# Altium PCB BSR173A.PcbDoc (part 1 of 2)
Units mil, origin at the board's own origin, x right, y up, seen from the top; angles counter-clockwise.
Board outline 3000 x 1500 mil, 4 copper layers (Top Layer, Signal Layer 1, Signal Layer 2, Bottom Layer), stack 61.2 mil thick; 64 components, 17 nets, 119 pads, 82 vias.
Unrouted connection lines stored in the file: 2.
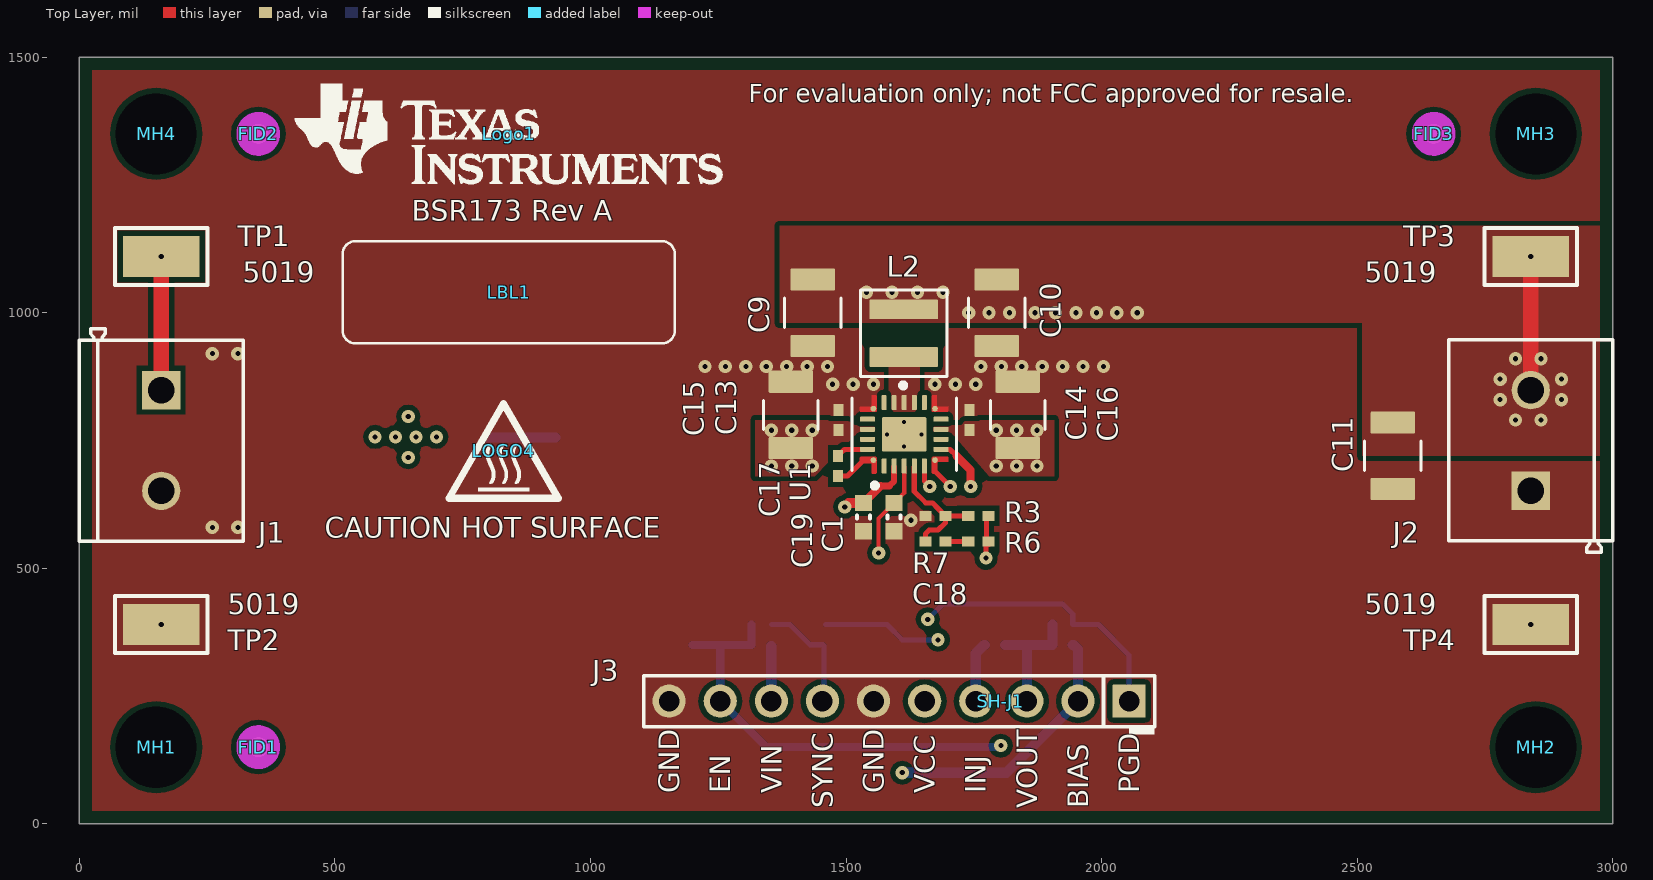
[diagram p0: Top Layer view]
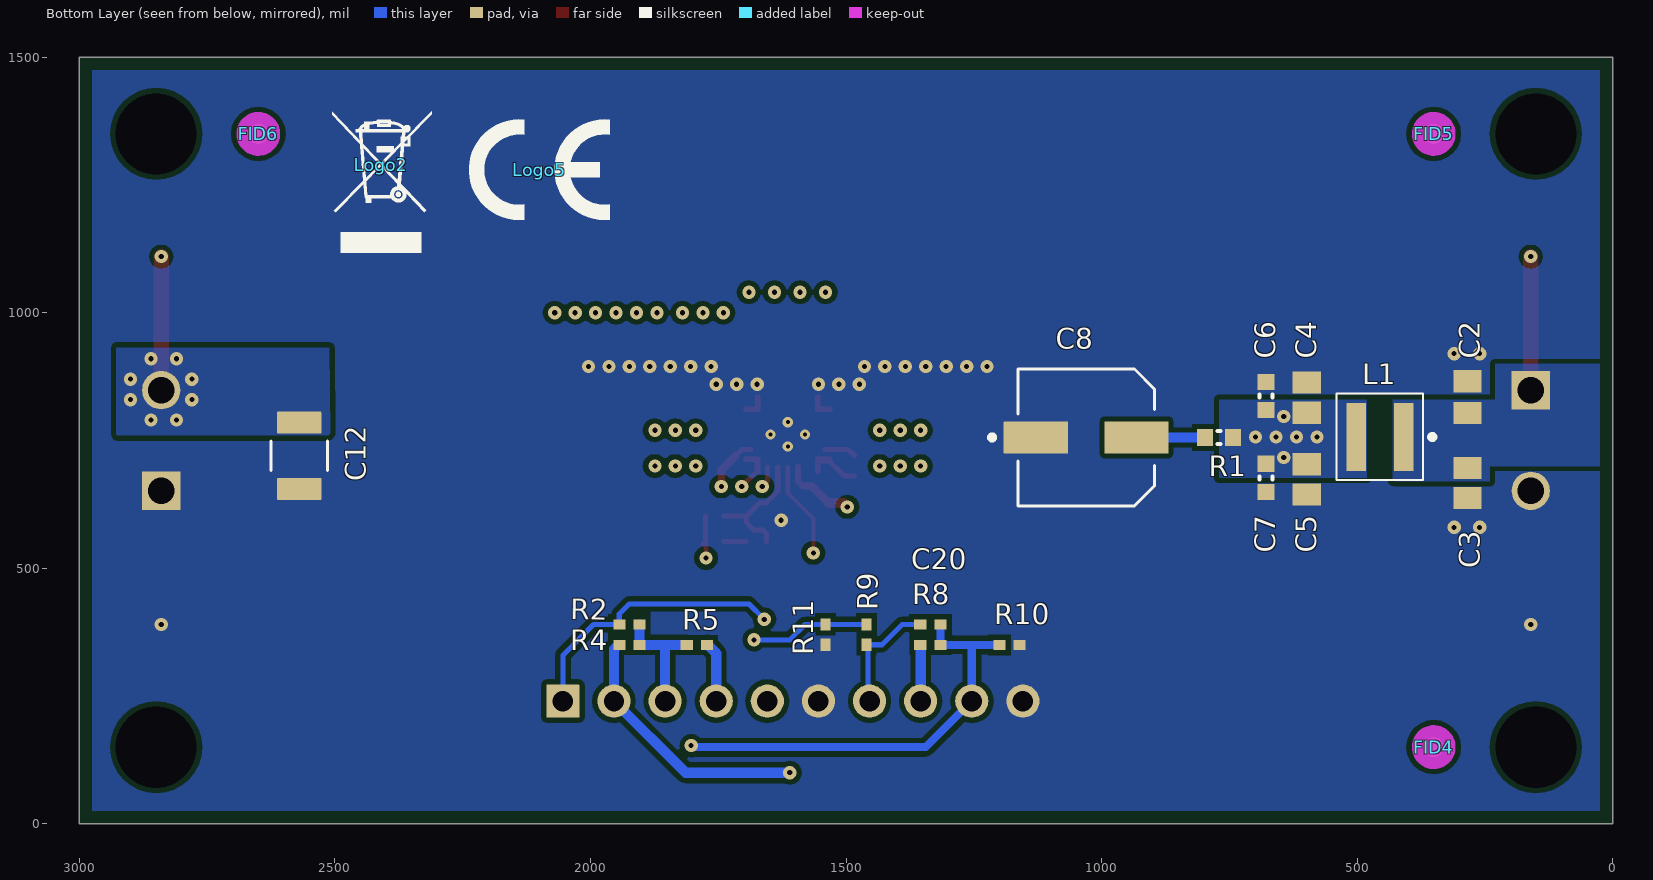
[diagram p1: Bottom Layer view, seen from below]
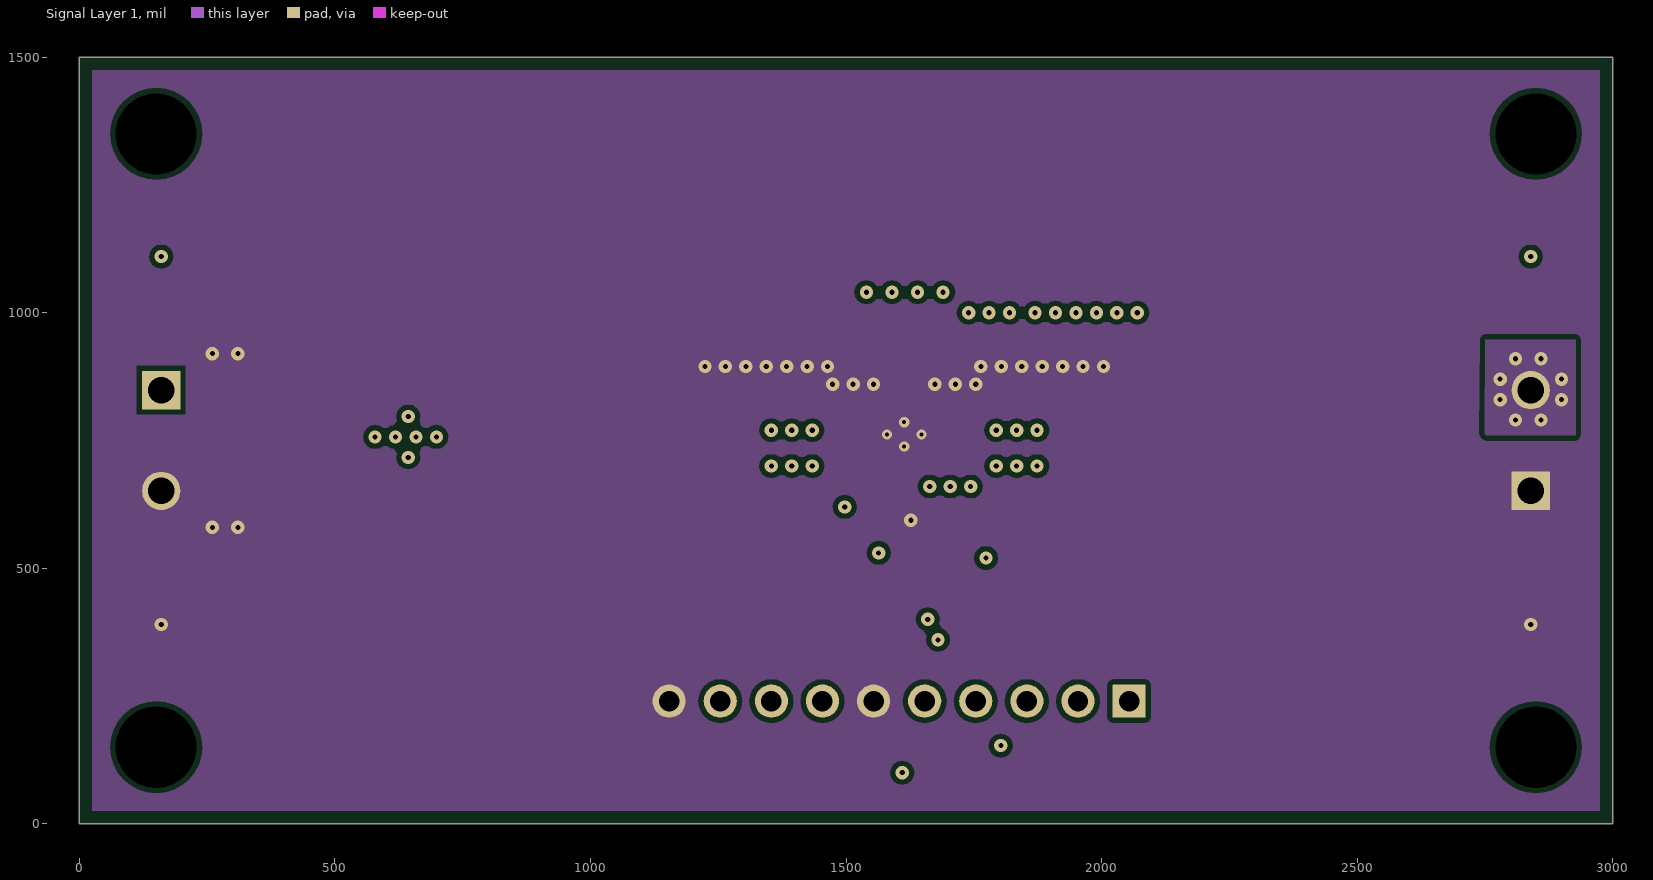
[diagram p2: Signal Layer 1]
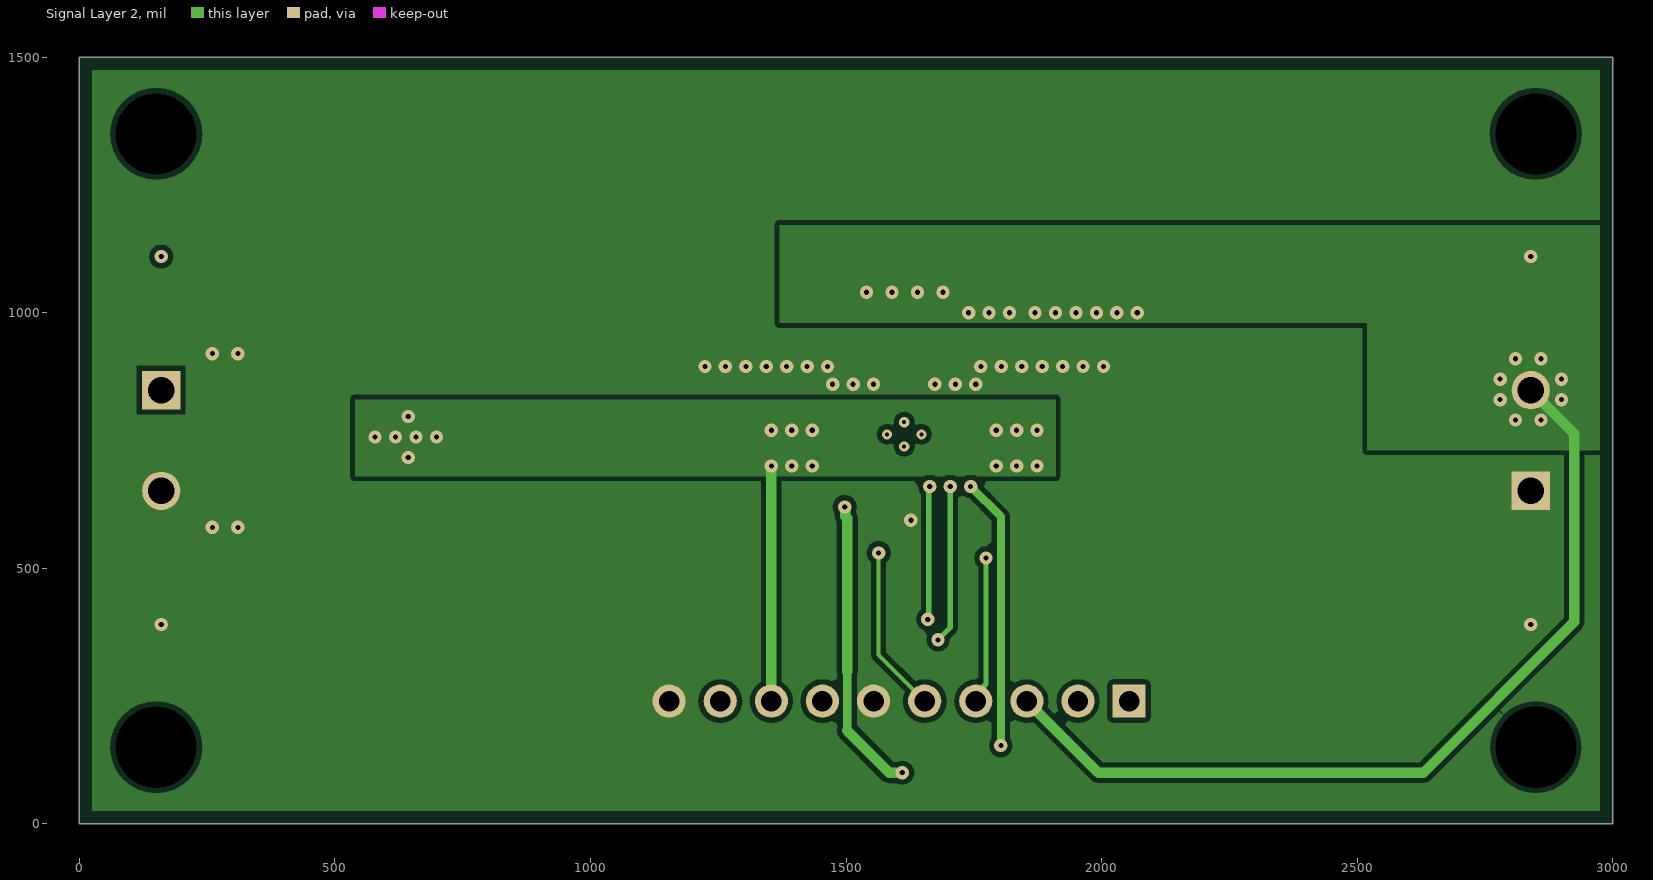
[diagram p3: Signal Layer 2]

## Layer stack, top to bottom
Top Solder: solder mask 0.4, Solder Resist, Dk 3.5
Top Layer: signal copper 2.8
Dielectric 1: prepreg 5, FR-4 High Tg, Dk 4.2
Signal Layer 1: signal copper 2.8
Dielectric 2: core 40, FR-4 High Tg, Dk 4.2
Signal Layer 2: signal copper 2.8
Dielectric 3: prepreg 5, FR-4 High Tg, Dk 4.2
Bottom Layer: signal copper 2.8
Bottom Solder: solder mask 0.4, Solder Resist, Dk 3.5

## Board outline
0,0 0,1500 3000,1500 3000,0

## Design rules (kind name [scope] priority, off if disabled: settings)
AcuteAngle [All] p1: minimum=4.50000000000000E+0001 checktracksonly=FALSE
AssemblyTestPointUsage [All] p1: valid=2
BoardOutlineClearance BoardOutlineClearance_1 [HasFootprint('Edge_Connector_EDAC_12x2')] p1: gap=0 ignorepadtopadclearanceinfootprint=FALSE
BoardOutlineClearance BoardOutlineClearance_MountingHoles [OnCopper and InComponentClass('Mounting Holes')] p2: gap=40 ignorepadtopadclearanceinfootprint=FALSE
BoardOutlineClearance BoardOutlineClearance_Poly [OnCopper and IsPoly] p3: gap=25 ignorepadtopadclearanceinfootprint=FALSE
BoardOutlineClearance [OnCopper and Not InComponentClass('Logo') and not InComponentClass('FiducialMark') and not InRegion(1000,500,4000,800) and not InPoly] p4: gap=65 ignorepadtopadclearanceinfootprint=FALSE
Clearance "Stitching VIN_PIN" [IsStitchingVia and InNet('VIN_PIN') vs (IsVia and (Not IsStitchingVia)) Or IsPad] p1: gap=9 ignorepadtopadclearanceinfootprint=FALSE
Clearance Clearance_Keepouts [((IsTrack Or IsArc) And Not InPoly) And IsFree and IsKeepOut vs ((IsTrack Or IsArc) And Not InPoly) And IsFree and IsKeepOut] p2: gap=0 ignorepadtopadclearanceinfootprint=FALSE
Clearance Clearance_Poly [InPolygon] p3: gap=10 ignorepadtopadclearanceinfootprint=FALSE
Clearance Clearance_FiducialMark [IsKeepOut and InComponentClass('FiducialMark') vs IsPad and InComponentClass('FiducialMark')] p4: gap=0 ignorepadtopadclearanceinfootprint=FALSE
Clearance [All] p5: gap=7.87 ignorepadtopadclearanceinfootprint=FALSE except(0: Arc-Hole Track-Hole SMDPad-Hole THPad-Hole Via-Hole Fill-Hole Poly-Hole Region-Hole Text-Hole)
ComponentClearance ComponentClearance_MountingHoles_FiducialMarks [InComponentClass('Mounting Holes') vs InComponentClass('FiducialMark')] p1: gap=50 collisioncheckmode=3 verticalgap=10 showdistances=FALSE
ComponentClearance ComponentClearance_Shunt [InComponentClass('Header') vs InComponentClass('Shunt')] p2: gap=0 collisioncheckmode=3 verticalgap=0 showdistances=FALSE
ComponentClearance ComponentClearance_Logo [InComponentClass('Logo')] p3: gap=50 collisioncheckmode=3 verticalgap=10 showdistances=FALSE
ComponentClearance ComponentClearance_ScrewToNut [(HasFootprint('NY PMS 440 0025 PH')) vs (HasFootprint('Keystone_1902C'))] p4: gap=5 collisioncheckmode=3 verticalgap=10 showdistances=FALSE
ComponentClearance ComponentClearance_MountingHoles [InComponentClass('Mounting Holes')] p5: gap=0 collisioncheckmode=3 verticalgap=100000 showdistances=FALSE
ComponentClearance ComponentClearance_SmallPassives [HasFootprint('0201*') or HasFootprint('0402*') or HasFootprint('0508') or HasFootprint('0603*') or HasFootprint('0612') or HasFootprint('0805*') or HasFootprint('0815*') or HasFootprint('0830*') or HasFootprint('1206*') or HasFootprint('1210*') or HasFootprint('1808*') or HasFootprint('1812*') or HasFootprint('1825*') or HasFootprint('2010*') or HasFootprint('2220*') or HasFootprint('2225*') or HasFootprint('2512*') or HasFootprint('2728*') or HasFootprint('3518*') vs HasFootprint('0201*') or HasFootprint('0402*') or HasFootprint('0508') or HasFootprint('0603*') or HasFootprint('0612') or HasFootprint('0805*') or HasFootprint('0815*') or HasFootprint('0830*') or HasFootprint('1206*') or HasFootprint('1210*') or HasFootprint('1808*') or HasFootprint('1812*') or HasFootprint('1825*') or HasFootprint('2010*') or HasFootprint('2220*') or HasFootprint('2225*') or HasFootprint('2512*') or HasFootprint('2728*') or HasFootprint('3518*')] p6: gap=14.96 collisioncheckmode=3 verticalgap=10 showdistances=FALSE
ComponentClearance ComponentClearance_THtoSMT [IsThruComponent vs IsSMTComponent] p7: gap=40 collisioncheckmode=3 verticalgap=30 showdistances=FALSE
ComponentClearance ComponentClearance_THtoTH [IsThruComponent vs IsThruComponent] p8: gap=30 collisioncheckmode=3 verticalgap=30 showdistances=FALSE
ComponentClearance [All] p9: gap=30 collisioncheckmode=3 verticalgap=10 showdistances=FALSE
DiffPairsRouting [All] p1: maxlimit=100 minlimit=10 mostfreqgap=10 toplayer_minwidth=15 toplayer_maxwidth=15 toplayer_prefwidth=15 midlayer1_minwidth=15 midlayer1_maxwidth=15 midlayer1_prefwidth=15 midlayer2_minwidth=15 midlayer2_maxwidth=15 midlayer2_prefwidth=15 bottomlayer_minwidth=15 bottomlayer_maxwidth=15 bottomlayer_prefwidth=15 maxuncoupledlength=1000
FabricationTestPointUsage TestPointUsage [All] p1: valid=2 allowmultiple=FALSE
FabricationTestpoint Testpoint [All] p1: side=3 testpointundercomponent=TRUE minsize=40 maxsize=100 preferedsize=60 minholesize=0 maxholesize=40 preferedholesize=32 testpointgrid=1 allowsidetop=TRUE allowsidebottom=TRUE usegrid=TRUE gridtolerance=0.01
FanoutControl Fanout_LCC [IsLCC] p1: bgadir=Out bgaviamode=Centered fanoutstyle=Auto fanoutdirection=Alternating viagrid=1 // Fanout_LCC (Default Rule)
FanoutControl Fanout_BGA [IsBGA] p2: bgadir=Out bgaviamode=Centered fanoutstyle=Auto fanoutdirection=Alternating viagrid=1 // Fanout_BGA (Default Rule)
FanoutControl Fanout_Default [All] p4: bgadir=Out bgaviamode=Centered fanoutstyle=Auto fanoutdirection=Alternating viagrid=1 // Fanout_Default (Default Rule)
FanoutControl Fanout_Small [(CompPinCount < 5)] p5: bgadir=Out bgaviamode=Centered fanoutstyle=Auto fanoutdirection=OutThenIn viagrid=1 // Fanout_Small (Default Rule)
HoleSize [All] p1: absolutevalues=TRUE maxlimit=251 minlimit=7.87 maxpercent=80.000 minpercent=20.000
MinimumAnnularRing MinimumAnnularRing_ThermalPadVias [IsVia and InAnyComponent] p1: minimumring=5.91
MinimumAnnularRing [All] p2: minimumring=7
MinimumSolderMaskSliver MinimumSolderMaskSliver_Logo [InComponentClass('Logo') vs InComponentClass('Logo')] p1: minsoldermaskwidth=0.7
MinimumSolderMaskSliver [All] p2: minsoldermaskwidth=3.94
PlaneConnect [All] p1: planeconnectstyle=Direct reliefexpansion=10 reliefentries=4 reliefconductorwidth=10 reliefairgap=10
PolygonConnect [All] p1: connectstyle=Direct reliefconductorwidth=10 reliefentries=4 polygonreliefangle="90 Angle" airgapwidth=10
RoutingVias ThermalPadVias [IsVia and InAnyComponent] p1: holewidth=7.87 width=19.68 viastyle="Through Hole" minholewidth=7.87 minwidth=19.68 maxholewidth=12.99 maxwidth=23.62
RoutingVias [All] p2: holewidth=16 width=34 viastyle="Through Hole" minholewidth=7.87 minwidth=20 maxholewidth=40 maxwidth=65
SilkToBoardRegionClearance [Not ((IsComment or IsDesignator) And (Hide <> 'False')) and not InRegion(1000,500,4000,800)] p1:
SilkToSilkClearance SilkToSilkClearance_Pb-FreeLogo [(HasFootprint('Pb-Free_Overlay_Medium') OR HasFootprint('Pb-Free_Overlay_Small')) vs (HasFootprint('Pb-Free_Overlay_Medium') OR HasFootprint('Pb-Free_Overlay_Small'))] p1: silktosilkclearance=0
SilkToSilkClearance [All] p2: silktosilkclearance=4
SilkToSolderMaskClearance SilkToComponentPadClearance [(IsPad or IsFill or IsRegion) and InAnycomponent] p1: minsilkscreentomaskgap=5 clearancetoexposedcopper=TRUE
SilkToSolderMaskClearance "Silk to Solder Mask Opening" [All] p2: minsilkscreentomaskgap=4 clearancetoexposedcopper=FALSE
SolderMaskExpansion [All] p1: expansion=1.97 istentingtop=FALSE
Width [All] p1: maxlimit=200 minlimit=6 preferedwidth=10 checkconnectedcopper=TRUE
15 further rules are at their usual default settings.

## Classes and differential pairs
component class Shunt: SH-J1
component class Label: LBL1
component class Header: J3
component class BSR173A: C1 C2 C3 C4 C5 C6 C7 C8 C9 C10 C11 C12 C13 C14 C15 C16 C17 C18 C19 C20 C23 D1 J1 J2 J3 J7 L1 L2 L-FLT L? PL1 R1 R2 R3 R4 R5 R6 R7 R8 R9 R10 R11 R13 R14 R15 R? TP1 TP2 TP3 TP4 TP11 TP13 TP17 TP? U1
component class Logo: Logo1
component class AssemblyNote: ZZ1 ZZ2 ZZ3 ZZ4 ZZ5 ZZ6
component class BSR173A_Hardware: !PCB FID1 FID2 FID3 FID4 FID5 FID6 LBL1 Logo1 Logo2 Logo3 LOGO4 Logo4 Logo5 Logo10 MH1 MH2 MH3 MH4 SH-J1 ZZ1 ZZ2 ZZ3 ZZ4 ZZ5 ZZ6
component class FiducialMark: FID1 FID2 FID3 FID4 FID5 FID6

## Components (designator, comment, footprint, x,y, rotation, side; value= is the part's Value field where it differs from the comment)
C1 "C0603C105K4RACAUTO" 0603L 1593.94,600 r270 top value=1uF
C2 "CGA4J3X7R1H225K125AB" 0805L#1 283.58,833 r90 bottom value=2.2uF
C3 "CGA4J3X7R1H225K125AB" 0805L#2 283.58,667 r270 bottom value=2.2uF
C4 "CGA4J3X7R1H225K125AB" 0805L#2 598.5,833.9 r90 bottom value=2.2uF
C5 "CGA4J3X7R1H225K125AB" 0805L#2 598.5,673.9 r270 bottom value=2.2uF
C6 "CGA3E3X7R1H474K080AE" 0603L 678.5,836.9 r90 bottom value=0.47uF
C7 "CGA3E3X7R1H474K080AE" 0603L 678.5,676.9 r270 bottom value=0.47uF
C8 "EEE-FN1H680XL" FP-EEE-FN1H680XL_RADIAL-MFG 1030,756 r180 bottom value=68µF
C9 "CGA6P1X7S1A476M250AC" FP-CGA6P1X7S1A476M250AC_1210-MFG 1435,1000 r270 top value=47µF
C10 "CGA6P1X7S1A476M250AC" FP-CGA6P1X7S1A476M250AC_1210-MFG 1795,1000 r270 top value=47µF
C11 "CGA6P1X7S1A476M250AC" FP-CGA6P1X7S1A476M250AC_1210-MFG 2570,720 r270 top value=47µF
C12 "CGA6P1X7S1A476M250AC" FP-CGA6P1X7S1A476M250AC_1210-MFG 2570,720 r270 bottom value=47µF
C13 "GRM155R71H223KA12D" 0402L 1485,790 r90 top value=0.022uF
C14 "GRM155R71H223KA12D" 0402L 1742,790 r90 top value=0.022uF
C15 "CNA6P1X7R1H106K250AE" FP-CNA6P1X7R1H106K250AE_1210-MFG 1392,800 r90 top value=10µF
C16 "CNA6P1X7R1H106K250AE" FP-CNA6P1X7R1H106K250AE_1210-MFG 1836,800 r90 top value=10µF
C17 "C0402C104K8RACTU" 0402L 1483.94,700 r270 top value=0.1uF
C18 "CGA2B2NP01H220J050BA" 0402L 1675.16,552 r0 top value=22pF
C19 "C0603C105K4RACAUTO" 0603L 1533.94,600 r90 top value=1uF
C20 "CGA2B2X7R1H102K050BA" 0402L 1335,390 r180 bottom value=1000pF
FID1 "Fiducial" Fiducial10-20 350,150 r0 top
FID2 "Fiducial" Fiducial10-20 350,1350 r0 top
FID3 "Fiducial" Fiducial10-20 2650,1350 r0 top
FID4 "Fiducial" Fiducial10-20 350,150 r180 bottom
FID5 "Fiducial" Fiducial10-20 350,1350 r180 bottom
FID6 "Fiducial" Fiducial10-20 2650,1350 r180 bottom
J1 "1729018" Phoenix_1729018 160,750 r270 top
J2 "1729018" Phoenix_1729018 2840,750 r90 top
J3 "TSW-110-07-G-S" TSW-110-07-G-S 1603.94,240 r180 top
L1 "XGL4020-102MEC" FP-XGL4020-102MEC_SMT_IND_4MM0_4MM0-MFG 455.16,756.9 r0 bottom
L2 "XGL4030-761MEC" FP-XGL4030-761MEC_SMD_IND_4MM0_4MM0-MFG 1613,960 r90 top value=0.76uH
LBL1 "THT-14-423-10" Label_650x200 840,1040 r180 top
Logo1 "Texas Instruments" TI_Stacked_Overlay_Small 840,1350 r0 top
Logo2 "WEEE logo" WEEE_Minimum 2410,1290 r180 bottom
Logo3 "FCC disclaimer" FCC_disclaimer 7341.5,-892 r90 top
LOGO4 "CAUTION HOT SURFACE" IEC_HotSurface_Small 830,730 r0 top
Logo5 "CE Mark" CE_Mark_5mm 2100,1280 r180 bottom (schematic designator LOGO5)
MH1 "MTG_NoPads" MTG_159mil 150,150 r0 top
MH2 "MTG_NoPads" MTG_159mil 2850,150 r0 top
MH3 "MTG_NoPads" MTG_159mil 2850,1350 r0 top
MH4 "MTG_NoPads" MTG_159mil 150,1350 r0 top
R1 "CRCW06030000Z0EA" 0603L 770,756 r180 bottom value=0
R2 "CRCW0402100KFKED" 0402L 1923.94,390 r180 bottom value=100k
R3 "CRCW0402100KFKED" 0402L 1758.94,602 r0 top value=100k
R4 "CRCW04021R00FKED" 0402L 1923.94,350 r0 bottom value=1.00
R5 "CRCW040249R9FKED" 0402L 1791.94,350 r180 bottom value=49.9
R6 "CRCW04021K00FKED" 0402L 1758.94,552 r180 top value=1.00k
R7 "CRCW040224K9FKED" 0402L 1674.84,602 r180 top value=24.9k
R8 "CRCW0402255KFKED" 0402L 1335,350 r0 bottom value=255k
R9 "CRCW04020000Z0ED" 0402L 1460,370 r270 bottom value=0
R10 "CRCW0402100KFKED" 0402L 1180,350 r180 bottom value=100k
R11 "CRCW0402100KFKED" 0402L 1540,370 r270 bottom value=100k
SH-J1 "SNT-100-BK-G" SNT-100-BK-G 1803,240 r180 top value=1x2
TP1 "5019" Keystone_5019 160,1110 r180 top
TP2 "5019" Keystone_5019 160,390 r0 top
TP3 "5019" Keystone_5019 2840,1110 r180 top
TP4 "5019" Keystone_5019 2840,390 r180 top
U1 "LM64460APPQRYFRQ1" RYF0022A-MFG 1613.94,762.13 r90 top
ZZ1 "This Assembly Note is for PCB labels only" AssemblyNoteLabel 200,2620 r0 top
ZZ2 "These assemblies are ESD sensitive, ESD precautions shall be observed." AssemblyNote 190,2500 r0 top
ZZ3 "These assemblies must be clean and free from flux and all contaminants. Use of no clean flux is not acceptable." AssemblyNote 190,2380 r0 top
ZZ4 "These assemblies must comply with workmanship standards IPC-A-610 Class 2, unless otherwise specified." AssemblyNote 190,2260 r0 top
ZZ5 "These assemblies must comply with workmanship standards IPC-A-610 Class 2, unless otherwise specified." AssemblyNote 190,2140 r0 top
ZZ6 "These assemblies must comply with workmanship standards IPC-A-610 Class 2, unless otherwise specified." AssemblyNote 190,2030 r0 top

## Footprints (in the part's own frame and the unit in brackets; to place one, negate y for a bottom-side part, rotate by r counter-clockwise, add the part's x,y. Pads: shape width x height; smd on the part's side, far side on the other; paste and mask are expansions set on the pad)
0402L [mm] "0402 from SM-752 data"
  rect 0.6x0.5 smd: 1(-0.5,0) 2(0.5,0)
  body extent -0.55,-0.3 0.55,0.3, height 0.6
0603L [mm] "0603 from SM-752 data"
  rect 0.8x0.85 smd: 1(-0.7,0) 2(0.7,0)
  silkscreen extent -0.07,-0.32 0.07,0.32, body extent -0.87,-0.47 0.87,0.47, height 1
0805L#1 [mm] "0805 from SM-752 data"
  rect 1.1x1.4 smd: 1(-0.75,0) 2(0.838,0)
  body extent -1.1,-0.72 1.1,0.72, height 1.45
0805L#2 [mm] "0805 from SM-752 data"
  rect 1.1x1.4 smd: 1(-0.75,0) 2(0.75,0)
  body extent -1.1,-0.72 1.1,0.72, height 1.45
AssemblyNote [mil] "Assembly Note"
AssemblyNoteLabel [mil] "Assembly Note for PCB Labels"
CE_Mark_5mm [mil] "Minimum text height for CE Mark"
  silkscreen extent -138,-98 138,98
FCC_disclaimer [mil]
Fiducial10-20 [mm]
  round 1 smd mask+0.5: 1(0,0)
  Top Layer keep-out circle w1.178: c0,0 r0.5
FP-CGA6P1X7S1A476M250AC_1210-MFG [mm]
  rrect9% 1.1x2.2 smd paste+0 mask+0: 1(-1.65,0) 2(1.65,0)
  silkscreen extent -0.72,-1.4 0.72,1.4, body extent -2.3,-1.5 2.3,1.5, height 0.25
FP-CNA6P1X7R1H106K250AE_1210-MFG [mm]
  rrect9% 1.1x2.2 smd paste+0 mask+0: 1(-1.65,0) 2(1.65,0)
  silkscreen extent -0.72,-1.35 0.72,1.35, body extent -2.3,-1.45 2.3,1.45, height 0.25
FP-EEE-FN1H680XL_RADIAL-MFG [mm]
  rrect6% 3.2x1.6 smd paste+0 mask+0: 1(-2.5,0) 2(2.5,0)
  silkscreen extent -4.8,-3.4 3.4,3.4, body extent -3.65,-3.3 3.65,3.3, height 8
FP-XGL4020-102MEC_SMT_IND_4MM0_4MM0-MFG [mm]
  rrect10% 0.98x3.4 smd paste+0 mask+0: 1(-1.185,0) 2(1.185,0)
  silkscreen extent -2.72,-2.15 2.15,2.15, body extent -2,-2 2,2, height 2.1
FP-XGL4030-761MEC_SMD_IND_4MM0_4MM0-MFG [mm]
  rrect10% 0.98x3.4 smd paste+0 mask+0: 1(-1.185,0) 2(1.185,0)
  silkscreen extent -2.15,-2.15 2.15,2.15, body extent -2.25,-2.25 2.25,2.25, height 0.25
IEC_HotSurface_Small [mil]
  silkscreen extent -107,-93 107,92
Keystone_5019 [mm] "Test Point, Miniature, SMT"
  rect 3.8x2.03 smd: 1(0,0)
  silkscreen extent -2.31,-1.41 2.31,1.41, body extent -1.9,-1.02 1.9,1.02, height 2.29
Label_650x200 [mil] "Thermal Transfer Label"
  round 1 on Mech13: 0(0,0)
  silkscreen extent -325,-100 325,100, body extent -325,-100 325,100, height 1
MTG_159mil [mil] "159mil Non Plated Hole"
  round 150 hole 159 unplated: 1(0,0)
Phoenix_1729018 [mm] "Phoenix Contact"
  rect 1.905x1.905 hole 1.3: 1(-2.5,0)
  round 1.9 hole 1.3: 2(2.5,0)
  silkscreen extent -5.56,-4.08 5.01,4.07, body extent -5.56,-4.08 5.01,4.07, height 10
RYF0022A-MFG [mm]
  round 0.278 smd paste+0 mask-1000: 1(-1.28,1.53) 7(-1.28,-1.53) 12(1.28,-1.53) 18(1.28,1.53)
  rrect40% 0.75x0.25 smd paste+0 mask-1000: 2(-1.575,1) 3(-1.575,0.5) 4(-1.575,0) 5(-1.575,-0.5) 6(-1.575,-1) 13(1.575,-1) 14(1.575,-0.5) 15(1.575,0) 16(1.575,0.5) 17(1.575,1)
  rrect40% 0.25x0.75 smd paste+0 mask-1000: 8(-0.75,-1.825) 9(-0.25,-1.825) 10(0.25,-1.825) 11(0.75,-1.825) 19(0.75,1.825) 20(0.25,1.825) 21(-0.25,1.825) 22(-0.75,1.825)
  rrect6% 1.7x2.2 smd paste-1000 mask-1000: 23(0,0)
  Top Layer region: 1.9,1.375 1.925,1.382 1.943,1.4 1.95,1.425 1.95,1.425 1.95,1.575 1.943,1.6 1.925,1.618 1.9,1.625 1.9,1.625 1.425,1.625 1.4,1.632 1.382,1.65 1.375,1.675 1.375,1.675 1.375,2.15 1.368,2.175 1.35,2.193 1.325,2.2 1.325,2.2 1.175,2.2 1.15,2.193 1.132,2.175 1.125,2.15 1.125,2.15 1.125,1.425 1.132,1.4 1.15,1.382 1.175,1.375 1.175,1.375
  Top Layer region: 1.9,-1.375 1.925,-1.382 1.943,-1.4 1.95,-1.425 1.95,-1.425 1.95,-1.575 1.943,-1.6 1.925,-1.618 1.9,-1.625 1.9,-1.625 1.425,-1.625 1.4,-1.632 1.382,-1.65 1.375,-1.675 1.375,-1.675 1.375,-2.15 1.368,-2.175 1.35,-2.193 1.325,-2.2 1.325,-2.2 1.175,-2.2 1.15,-2.193 1.132,-2.175 1.125,-2.15 1.125,-2.15 1.125,-1.425 1.132,-1.4 1.15,-1.382 1.175,-1.375 1.175,-1.375
  Top Layer region: -1.9,-1.375 -1.925,-1.382 -1.943,-1.4 -1.95,-1.425 -1.95,-1.425 -1.95,-1.575 -1.943,-1.6 -1.925,-1.618 -1.9,-1.625 -1.9,-1.625 -1.425,-1.625 -1.4,-1.632 -1.382,-1.65 -1.375,-1.675 -1.375,-1.675 -1.375,-2.15 -1.371,-2.169 -1.36,-2.185 -1.344,-2.196 -1.325,-2.2 -1.325,-2.2 -1.175,-2.2 -1.15,-2.193 -1.132,-2.175 -1.125,-2.15 -1.125,-2.15 -1.125,-1.425 -1.132,-1.4 -1.15,-1.382 -1.175,-1.375 -1.175,-1.375
  Top Layer region: -1.9,1.375 -1.925,1.382 -1.943,1.4 -1.95,1.425 -1.95,1.425 -1.95,1.575 -1.943,1.6 -1.925,1.618 -1.9,1.625 -1.9,1.625 -1.425,1.625 -1.4,1.632 -1.382,1.65 -1.375,1.675 -1.375,1.675 -1.375,2.15 -1.371,2.169 -1.36,2.185 -1.344,2.196 -1.325,2.2 -1.325,2.2 -1.175,2.2 -1.15,2.193 -1.132,2.175 -1.125,2.15 -1.125,2.15 -1.125,1.425 -1.132,1.4 -1.15,1.382 -1.175,1.375 -1.175,1.375
  silkscreen extent -2.67,-2.6 1.8,2.6, body extent -2.05,-2.3 2.05,2.3, height 0.25
SNT-100-BK-G [mil] "Samtec STEP model"
  round 1 on Mech3: 0(0,0)
  body extent -100,-50 100,50, height 344
TI_Stacked_Overlay_Small [mil]
  silkscreen extent -418,-98 418,98
TSW-110-07-G-S [mil] "Samtec 100mil, 1x10, 230 mil above insulator"
  rrect6% 64.96x64.96 hole 40: 1(-450,0)
  round 64.96 hole 40: 2(-350,0) 3(-250,0) 4(-150,0) 5(-50,0) 6(50,0) 7(150,0) 8(250,0) 9(350,0) 10(450,0)
  silkscreen extent -500,-50 500,65, body extent -500,-50 500,50, height 330
WEEE_Minimum [mil] "WEEElie bin"
  silkscreen extent -95,-172 99,104

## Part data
C1 C19: library part CMP-0084111-1, "CAP, CERM, 1 µF, 16 V,+/- 10%, X7R, AEC-Q200 Grade 1, 0603", Cap_Case=0603, Manufacturer=Kemet, TempCo=X7R, Tolerance_%=10%, Value2=16V, ValueDisplayed=1µF
C2 C3 C4 C5: library part CMP-0007977-2, "CAP, CERM, 2.2 uF, 50 V, +/- 10%, X7R, AEC-Q200 Grade 1, 0805", Cap_Case=0805, Manufacturer=TDK, Supplier Part Number 1=445-174216-1-ND, TempCo=X7R, Tolerance_%=10%, Value1="0.003288 ohm", Value2=50V, ValueDisplayed=2.2uF
C6 C7: library part CMP-0007097-4, "CAP, CERM, 0.47 uF, 50 V, +/- 10%, X7R, AEC-Q200 Grade 1, 0603", Cap_Case=0603, Manufacturer=TDK, Supplier Part Number 1=445-172475-1-ND, TempCo=X7R, Tolerance_%=10%, Value1=Unknown, Value2=50V, ValueDisplayed=0.47uF
C8: library part CMP-0092865-1, "68µF 50V Aluminum Electrolytic Capacitors Radial, Can - SMD 680mOhm @ 100kHz 2000 Hrs @ 105°C", Digikey Part Number=10-EEE-FN1H680XLCT-ND, Leakage Current=34uA, Manufacturer=Panasonic, Mouser Part Number=667-EEE-FN1H680XL, Operating Temperature Range="-55°C to +105°C", Tolerance_%=20%, ValueDisplayed=68uF
C9 C10 C11 C12: library part CMP-0092443-1, "Multilayer Ceramic Capacitor 47uF 20% 10V 1210 T/R", Digikey Part Number=445-CGA6P1X7S1A476M250ACCT-ND, Manufacturer=TDK, Mouser Part Number=810-CGA6P1X7S1A47625, Operating Temperature Range="-55°C to +125°C", TempCo=22%, Temperature Characteristic=X7S, Tolerance_%=20%, ValueDisplayed=47uF
C13 C14: library part CMP-0006684-2, "CAP, CERM, 0.022 uF, 50 V, +/- 10%, X7R, 0402", Cap_Case=0402, Manufacturer=MuRata, Supplier Part Number 1=490-3884-1-ND, TempCo=X7R, Tolerance_%=10%, Value1=Unknown, Value2=50V, ValueDisplayed=0.022uF
C15 C16: library part CMP-0092450-1, "10uF @ ±10% 50V Ceramic Capacitor X7R 1210 (3225 Metric)", Digikey Part Number=445-180367-1-ND, Manufacturer=TDK, Mouser Part Number=810-CNA6P1X7R1H106K2, Operating Temperature Range="-55°C to +125°C", TempCo=15%, Temperature Characteristic=X7R, Tolerance_%=10%, ValueDisplayed=10uF
C17: library part CMP-0078241-1, "CAP, CERM, 0.1 µF, 10 V,+/- 10%, X7R, 0402", Cap_Case=0402, Manufacturer=Kemet, Supplier Part Number 1=399-3520-1-ND, TempCo=X7R, Tolerance_%=10%, Value2=10V, ValueDisplayed=0.1µF
C18: library part CMP-0006311-2, "CAP, CERM, 22 pF, 50 V, +/- 5%, C0G/NP0, AEC-Q200 Grade 1, 0402", Cap_Case=0402, Manufacturer=TDK, Supplier Part Number 1=445-12130-1-ND, TempCo=C0G/NP0, Tolerance_%=5%, Value1=Unknown, Value2=50V, ValueDisplayed=22pF
C20: library part CMP-0006314-2, "CAP, CERM, 1000 pF, 50 V, +/- 10%, X7R, AEC-Q200 Grade 1, 0402", Cap_Case=0402, Manufacturer=TDK, Supplier Part Number 1=445-5605-1-ND, TempCo=X7R, Tolerance_%=10%, Value1="2.25564 ohm", Value2=50V, ValueDisplayed=1000pF
FID1 FID2 FID3 FID4 FID5 FID6: library part CMP-0077181-1, "Fiducial mark.  There is nothing to buy or mount.", Manufacturer=N/A
J1 J2: library part CMP-0055486-1, "TERM BLOCK 2POS 5mm, TH", Manufacturer="Phoenix Contact", Supplier Part Number 1=651-1729018
J3: library part CMP-0075422-1, "Header, 100mil, 10x1, Gold, TH", Color=Black, Current_A=6.3A, Manufacturer=Samtec, Supplier Part Number 1=SAM1029-10-ND, Voltage_V=550V
L1: library part CMP-0086510-2, "Shielded Power Inductors", Manufacturer=Coilcraft
L2: library part CMP-0090843-1, "Power Inductor, shielded, composite, 0.76uH 20% tol, 5.5mOhms, SFR 72MHz, ISAT 5.6A, IRMS14.2ASMT, RoHS, halogen-free", Manufacturer=Coilcraft, Operating Temperature Range=to, Self Resonant Frequency=72MHz, Test Frequency=1MHz, Tolerance_%=20%
LBL1: library part CMP-0003625-1, "Thermal Transfer Printable Labels, 0.650\" W x 0.200\" H - 10,000 per roll", Manufacturer=Brady, Supplier Part Number 1=97C5133
Logo1: library part CMP-0074838-1, "Texas Instrument Corporate Signature"
Logo2: library part CMP-0074769-1
Logo3: library part CMP-0074847-1, "FCC_disclaimer"
LOGO4: library part CMP-0074837-2, "IEC 61010-1 Hot Surface Warning", Manufacturer="Texas Instruments"
Logo5: library part CMP-0074844-1
MH1 MH2 MH3 MH4: library part CMP-0078424-2, "PCB Mounting Hole, No Pad", Manufacturer=Any, PartNumber=N/A
R1: library part CMP-0025697-4, "RES, 0, 5%, 0.1 W, AEC-Q200 Grade 0, 0603", Manufacturer=Vishay-Dale, Power_W=100mW, Supplier Part Number 1=541-0.0GCT-ND, TempCo="200 ppm/C", Tolerance_%=5%, Value2=0.1W, Value_Code=0000, ValueDisplayed=0
R2 R3 R10 R11: library part CMP-0025950-3, "RES, 100 k, 1%, 0.063 W, AEC-Q200 Grade 0, 0402", Manufacturer=Vishay-Dale, Power_W=63mW, Supplier Part Number 1=541-100KLCT-ND, TempCo="100 ppm/C", Tolerance_%=1%, Value2=0.063W, Value_Code=100k
R4: library part CMP-0026129-2, "RES, 1.00, 1%, 0.063 W, AEC-Q200 Grade 0, 0402", Manufacturer=Vishay-Dale, Power_W=63mW, Supplier Part Number 1=541-1.00LLCT-ND, TempCo="100 ppm/C", Tolerance_%=1%, Value2=0.063W, Value_Code=1R00, ValueDisplayed=1.00
R5: library part CMP-0026404-2, "RES, 49.9, 1%, 0.063 W, AEC-Q200 Grade 0, 0402", Manufacturer=Vishay-Dale, Power_W=63mW, Supplier Part Number 1=541-49.9LCT-ND, TempCo="100 ppm/C", Tolerance_%=1%, Value2=0.063W, Value_Code=49R9, ValueDisplayed=49.9
R6: library part CMP-0026071-3, "RES, 1.00 k, 1%, 0.063 W, AEC-Q200 Grade 0, 0402", Manufacturer=Vishay-Dale, Power_W=63mW, Supplier Part Number 1=541-1.00KLCT-ND, TempCo="100 ppm/C", Tolerance_%=1%, Value2=0.063W, Value_Code=1k00, ValueDisplayed=1.00k
R7: library part CMP-0026196-2, "RES, 24.9 k, 1%, 0.063 W, AEC-Q200 Grade 0, 0402", Manufacturer=Vishay-Dale, Power_W=63mW, Supplier Part Number 1=541-24.9KLCT-ND, TempCo="100 ppm/C", Tolerance_%=1%, Value2=0.063W, Value_Code=24k9, ValueDisplayed=24.9k
R8: library part CMP-0026199-2, "RES, 255 k, 1%, 0.063 W, AEC-Q200 Grade 0, 0402", Manufacturer=Vishay-Dale, Power_W=63mW, Supplier Part Number 1=541-255KLCT-ND, TempCo="100 ppm/C", Tolerance_%=1%, Value2=0.063W, Value_Code=255k
R9: library part CMP-0026822-3, "RES, 0, 5%, 0.063 W, AEC-Q200 Grade 0, 0402", Manufacturer=Vishay-Dale, Power_W=63mW, Supplier Part Number 1=541-0.0JCT-ND, TempCo="200 ppm/C", Tolerance_%=5%, Value2=0.063W, Value_Code=0000, ValueDisplayed=0
SH-J1: library part CMP-0003623-3, "Shunt, 100mil, Gold plated, Black", Alternate Manufacturer=3M, Alternate PartNumber=969102-0000-DA, Manufacturer=Samtec, Supplier Part Number 1=SAM8858-ND
TP1 TP2 TP3 TP4: library part CMP-0055162-1, "Test Point, Miniature, SMT", Manufacturer=Keystone, Supplier Part Number 1=36-5019TR-ND
U1: library part CMP-0092919-2, "Automotive 3-V to 36-V, 6-A Synchronous Buck DC/DC Converter, Adjustable 1-34.2V, VQFN-FCRLF22", Manufacturer="Texas Instruments", Max Supply Voltage=36V, Min Supply Voltage=3V, Nominal Supply Current=0.6uA, Operating Temperature Range="-40°C to +150°C", Output Voltage=1-34.2V, Switching Frequency=200-2200kHz
ZZ1: library part CMP-0003616-3
ZZ2: library part CMP-0077236-1
ZZ3: library part CMP-0077237-1
ZZ4 ZZ5 ZZ6: library part CMP-0077238-1

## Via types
v1: diameter 26, hole 10, Top Layer to Bottom Layer, tented both sides, 74 vias
v2: diameter 19.68, hole 7.87, Top Layer to Bottom Layer, 4 vias
v3: diameter 26, hole 10, Top Layer to Bottom Layer, tented bottom, 4 vias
